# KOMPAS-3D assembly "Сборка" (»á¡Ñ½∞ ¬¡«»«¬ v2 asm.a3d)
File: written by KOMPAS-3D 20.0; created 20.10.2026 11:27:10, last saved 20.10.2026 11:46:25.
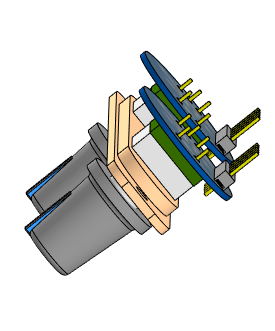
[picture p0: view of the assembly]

Document properties: Полное имя файла: D:\RicWork\Project-EPS32\box_compas\сборки компонентов\панель кнопок v2 asm.a3d

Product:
- Part/product: Сборка
    Масса: 0.0702532
  - Component [assembly]: Сборка  | qty 2  | Масса: 0.0191636; source file: ..\переключатели и кнопки\TZT_EC11 asm.a3d
  - Component [detail]: Деталь  | Масса: 0.0319261; source file: ..\корпус\панель кнопоr 2bt.m3d

Referenced files in D:\RicWork\Project-EPS32\box_compas\переключатели и кнопки\: TZT_EC11 asm.a3d
Referenced files in D:\RicWork\Project-EPS32\box_compas\корпус\: панель кнопоr 2bt.m3d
